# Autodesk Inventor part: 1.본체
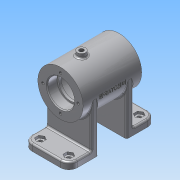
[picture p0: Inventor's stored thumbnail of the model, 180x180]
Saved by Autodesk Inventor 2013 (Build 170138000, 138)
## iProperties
Created: 2017-02
Part Number: 1.본체
Material: 알루미늄 6061
Document SubType Name: Modeling
Designer: Administrator
Density: 2.71 g/cm^3
Mass: 357.048 g
Surface Area: 419.607 cm^2
Volume: 131.752 cm^3
Author: Administrator
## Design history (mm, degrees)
sketch "스케치1"
  geometry: C1 r 27 at (0, 0); 1 further point
  constraints: 1 centre point, 1 coincident
  dimensions: "d0" = 54 diameter of C1
extrude "돌출1" new body sketch "스케치1" distance "d2" = 70; taper "d3" = 0 deg
sketch "스케치2"
  geometry: L1 (27, 70)-(-27, 70) reference; L2 (-27, 0)-(27, 0) reference; L3 (0, 0)-(0, 70); L4 (16, 70)-(16, 58); L5 (16, 58)-(14, 58); L6 (14, 58)-(14, 55); L7 (14, 55)-(22, 55); L8 (22, 55)-(22, 15); L9 (22, 15)-(14, 15); L10 (14, 15)-(14, 12); L11 (14, 12)-(16, 12); L12 (16, 12)-(16, 0)
  constraints: 20 end point, 4 parallel, 4 perpendicular, 2 collinear, 2 point on line, 1 midpoint, 1 vertical
  dimensions: "d4" = 32 diameter of L12 L3; "d6" = 28 diameter of L10 L3; "d7" = 44 diameter of L8 L3; "d8" = 28 diameter of L6 L3; "d9" = 32 diameter of L4 L3; "d10" = 40 distance of L7.end L8.end; "d11" = 12 distance of L4.start L4.end
revolve "회전1" sketch "스케치2" stored, may be unused: angle "d12" = 90 deg
chamfer "모따기1" distance "d13" = 1; stored, may be unused: second distance "d14" = 2, angle "d15" = 45 deg
fillet "모깎기1" dims "d16" = 3
fillet "모깎기2" dims "d17" = 0.3
node "작업 평면2"
  node "작업 평면1"
sketch "스케치3"
  geometry: L1 (-27, 0)-(-27, -60); L2 (-27, -60)-(27, -60); L3 (27, -60)-(27, 0); A1 r 27 centre (0, 0) between (-27, 0) and (27, 0) reference; 1 further point
  constraints: 6 end point, 2 point on circle, 2 tangent, 2 vertical, 1 perpendicular
  dimensions: "d19" = 60 distance of L2.end L3.end
extrude "돌출2" join sketch "스케치3" distance "d21" = 8; taper "d22" = 0 deg
sketch "스케치4"
  geometry: L1 (27, -60)-(-27, -60) reference; L2 (-27, -52)-(27, -52); L3 (27, -52)-(27, -60); L4 (27, -60)-(-27, -60); L5 (-27, -60)-(-27, -52); 3 further points
  constraints: 8 end point, 4 midpoint, 2 parallel, 1 horizontal, 1 perpendicular, 1 vertical alignment
  dimensions: "d23" = 8 distance of L2.end L3.end; "d25" = 54 distance of L3.end L4.end
extrude "돌출3" join sketch "스케치4" distance "d26" = 35; taper "d27" = 0 deg
fillet "모깎기3" dims "d28" = 10
sketch "스케치6"
  geometry: L1 (10, -11.804)-(14.5, -14.402); L2 (14.5, -14.402)-(14.5, -19.598); L3 (14.5, -19.598)-(10, -22.196); L4 (10, -22.196)-(5.5, -19.598); L5 (5.5, -19.598)-(5.5, -14.402); L6 (5.5, -14.402)-(10, -11.804); C1 r 4.5 at (10, -17); A1 r 10 centre (10, -17) between (0, -17) and (10, -27) reference; 2 further points
  constraints: 12 end point, 2 coincident, 1 centre point, 1 tangent, 1 vertical alignment, 13 other
  dimensions: "d29" = 9 diameter of C1
extrude "돌출4" cut sketch "스케치6" distance "d31" = 3; taper "d32" = 0 deg
sketch "스케치7"
  geometry: L1 (14.5, -14.402)-(14.5, -19.598) reference; C1 r 2.5 at (10, -17); 3 further points
  constraints: 1 centre point, 1 horizontal alignment, 1 midpoint, 1 vertical alignment
  dimensions: "d33" = 5 diameter of C1
extrude "돌출5" cut sketch "스케치7" stored distance "d35" = 3; taper "d36" = 0 deg
sketch "스케치8" dims "d40" = 42
  geometry: L1 (0, 0)-(0, 21); C1 r 17 at (0, 0) reference; 1 further point
  constraints: 2 coincident, 2 end point, 1 vertical, 1 vertical alignment, 2 other
hole "구멍1" sketch "스케치8" at (0, 21) diameter "d42" = 3.242; stored, may be unused: countersink angle "d46" = 90 deg, drill point angle "d48" = 118 deg; dims "d43" = 8, "d44" = 4, "d45" = 2, "d47" = 10
node "작업 평면3"
sketch "스케치9"
  geometry: L1 (27, 70)-(-27, 70) reference; C1 r 5 at (0, 45); 1 further point
  constraints: 1 centre point, 1 vertical alignment
  dimensions: "d53" = 25 distance from line of C1.centre L1; "d54" = 10 diameter of C1
extrude "돌출6" join sketch "스케치9" stored distance "d55" = 3; taper "d56" = 0 deg
sketch "스케치10"
  geometry: C1 r 5 at (0, 0) reference; 2 further points
  constraints: 1 coincident
hole "구멍2" sketch "스케치10" at (0, 0) diameter "d57" = 5.188; stored, may be unused: countersink angle "d61" = 90 deg, drill point angle "d63" = 0 deg; dims "d58" = 8, "d59" = 4, "d60" = 2, "d62" = 10
node "작업 평면4"
sketch "스케치11"
  geometry: L1 (27, 70)-(-27, 70) reference; L2 (27, 0)-(27, 70) reference; 2 further points
  constraints: 1 other
  dimensions: "d65" = 35 distance from line of point (0, 35) L1; "d66" = 27 distance from line of L2 point (0, 35)
feature "엠보싱1" sketch "스케치11" dims "d0" = 54, "d67" = 0.5, "d68" = 0
sketch "스케치13"
  geometry: L1 (0, 0)-(-16.339, -25.16); L2 (0, 0)-(0, -27); L3 (-21.371, -21.892)-(-11.307, -28.428); L4 (-21.371, -21.892)-(-19.37, -18.81); L5 (-11.307, -28.428)-(-9.306, -25.346); A1 r 27 centre (0, 0) between (0, -27) and (-19.37, -18.81) reference; 1 further point
  constraints: 10 end point, 3 point on circle, 2 perpendicular, 1 midpoint, 1 parallel, 1 vertical
  dimensions: "d69" = 33 deg angle of L2 L1; "d70" = 30 distance of L1.end L1.start; "d71" = 12 distance of L3.start L3.end
extrude "돌출7" join sketch "스케치13" stored distance "d72" = 12; taper "d73" = 0 deg
sketch "스케치14"
  geometry: L1 (0, 0)-(0, 12) reference; L2 (-12, 12)-(0, 12) reference; L3 (-12, 12)-(-12, 0) reference; L4 (0, 0)-(-12, 0) reference; C1 r 6 at (-6, 6); 3 further points
  constraints: 2 midpoint, 1 centre point, 1 horizontal alignment, 1 vertical alignment
  dimensions: "d74" = 12 diameter of C1
extrude "돌출8" cut sketch "스케치14" stored distance "d76" = 12; taper "d77" = 0 deg
sketch "스케치15"
  geometry: C1 r 6 at (0, 0) reference; 2 further points
  constraints: 1 coincident
hole "구멍3" sketch "스케치15" at (0, 0) diameter "d78" = 5.188; stored, may be unused: countersink angle "d82" = 90 deg, drill point angle "d84" = 0 deg; dims "d79" = 8, "d80" = 4, "d81" = 2, "d83" = 10
fillet "모깎기4" dims "d85" = 2
fillet "모깎기5" dims "d86" = 2
fillet "모깎기6" dims "d87" = 2
fillet "모깎기7" dims "d88" = 2
fillet "모깎기8" dims "d89" = 2
fillet "모깎기9" dims "d90" = 2
node "작업 평면5"
node "솔리드1"
pattern_linear "직사각형 패턴1" dims "d39" = 34
mirror "대칭1"
pattern_circular "원형 패턴1" dims angle "d50" = 360 deg
mirror "대칭2"
other parameters: "d18" = 17, "d52" = 32, "d64" = 32.25
